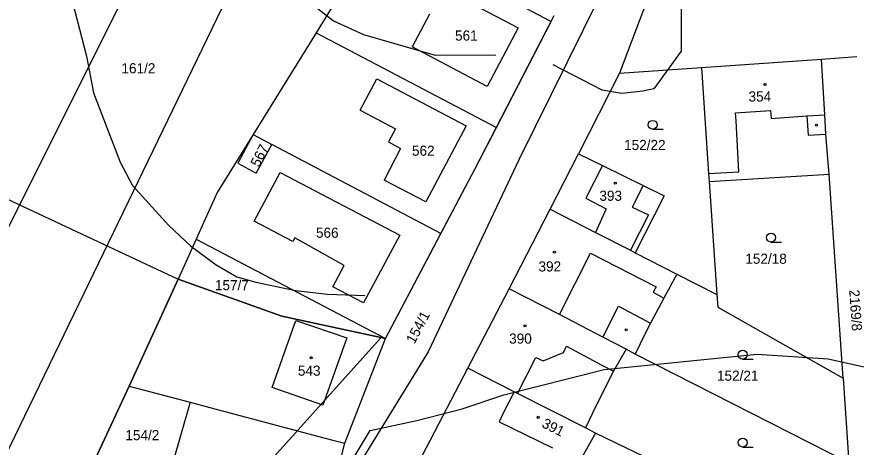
# Model space of a CAD drawing. Extents: x -555860 to -552701, y -1187050 to -1182291.
# Drawn here: x -554722 to -554581.3, y -1185302.4 to -1185230.2 of the extents above; entities that cross this region are included whole.
import ezdxf

# ---------------------------------------------------------------- set-up
doc = ezdxf.new("R2010")
doc.units = 0
for name, color, linetype in [('CYKLISTI_stav', 7, 'Continuous'), ('LEG_2b', 7, 'Continuous'), ('Level 25', 7, 'Continuous'), ('Level 32', 7, 'Continuous'), ('Level 40', 7, 'Continuous'), ('Level 41', 7, 'Continuous'), ('navrh_BV', 7, 'Continuous'), ('Poz předměty', 7, 'Continuous')]:
    doc.layers.add(name, color=color, linetype=linetype)

msp = doc.modelspace()

# ---------------------------------------------------------------- linework, layer by layer
at = {"layer": 'CYKLISTI_stav'}
for p, q in [((-554652.87, -1185229.81), (-554655.75, -1185235.27)), ((-554601.54, -1185246.33), (-554595.67, -1185245.93)), ((-554595.67, -1185245.93), (-554595.58, -1185247.27)), ((-554601.44, -1185247.68), (-554601.54, -1185246.33)), ((-554595.58, -1185247.27), (-554589.59, -1185246.86)), ((-554589.59, -1185246.86), (-554586.6, -1185246.65)), ((-554589.59, -1185246.86), (-554589.37, -1185250.05)), ((-554601.01, -1185256.23), (-554601.44, -1185247.68)), ((-554589.37, -1185250.05), (-554586.41, -1185249.88)), ((-554623.86, -1185255.18), (-554626.65, -1185260.66)), ((-554606.09, -1185256.51), (-554601.01, -1185256.23)), ((-554617.06, -1185258.49), (-554618.89, -1185262.12)), ((-554626.65, -1185260.66), (-554623.21, -1185262.45)), ((-554623.21, -1185262.45), (-554625, -1185266.39)), ((-554618.89, -1185262.12), (-554616.15, -1185263.46)), ((-554616.15, -1185263.46), (-554619.18, -1185269.37)), ((-554631.05, -1185280.15), (-554625.86, -1185269.85)), ((-554625.86, -1185269.85), (-554614.84, -1185275.52)), ((-554614.84, -1185275.52), (-554615.36, -1185276.41)), ((-554615.36, -1185276.41), (-554613.56, -1185277.39)), ((-554623.8, -1185283.93), (-554621.18, -1185278.72)), ((-554621.18, -1185278.72), (-554615.82, -1185281.59)), ((-554679.22, -1185292.41), (-554676.83, -1185285.56)), ((-554630.41, -1185286.52), (-554629.88, -1185285.43)), ((-554629.88, -1185285.43), (-554623.94, -1185288.63)), ((-554633.82, -1185287.93), (-554630.41, -1185286.52)), ((-554638.09, -1185293.4), (-554635.02, -1185287.37)), ((-554635.02, -1185287.37), (-554633.82, -1185287.93)), ((-554623.94, -1185288.63), (-554622.01, -1185289.67)), ((-554638.67, -1185293.1), (-554640.47, -1185296.55)), ((-554640.47, -1185296.55), (-554641.17, -1185298.14)), ((-554641.17, -1185298.14), (-554632.24, -1185302.52))]:
    msp.add_line(p, q, dxfattribs=at)
for points in [[(-554655.35, -1185228.5), (-554653.06, -1185224.13), (-554638, -1185232.07), (-554643.16, -1185241.89), (-554655.75, -1185235.27)], [(-554664.45, -1185245.89), (-554661.69, -1185240.61), (-554646.7, -1185248.53), (-554653.45, -1185261.25), (-554660.46, -1185257.6)], [(-554664.45, -1185245.89), (-554658.55, -1185249), (-554659.72, -1185251.2), (-554657.7, -1185252.3), (-554660.46, -1185257.6)], [(-554677.86, -1185256.31), (-554657.85, -1185266.84), (-554663.92, -1185278.2), (-554669.05, -1185275.52), (-554667.15, -1185271.91), (-554675.45, -1185267.31), (-554675.78, -1185267.92), (-554682.23, -1185264.5), (-554677.86, -1185256.31)], [(-554676.83, -1185285.56), (-554675.24, -1185281.13), (-554666.69, -1185284.05)], [(-554666.69, -1185284.05), (-554670.72, -1185295.35), (-554679.22, -1185292.41)]]:
    msp.add_lwpolyline(points, dxfattribs=at)
at = {"layer": 'Level 25'}
for p, q in [((-554615.43, -1185249.09), (-554613.68, -1185249.09)), ((-554595.61, -1185267.99), (-554593.86, -1185267.99)), ((-554600.36, -1185287.64), (-554598.61, -1185287.64)), ((-554600.35, -1185302.36), (-554598.6, -1185302.36))]:
    msp.add_line(p, q, dxfattribs=at)
for centre, radius in [((-554596.6, -1185241.59), 0.175), ((-554615.43, -1185248.34), 0.75), ((-554587.97, -1185248.41), 0.175), ((-554621.71, -1185258.11), 0.175), ((-554595.61, -1185267.24), 0.75), ((-554631.92, -1185269.69), 0.175), ((-554636.84, -1185282.05), 0.175), ((-554619.87, -1185282.72), 0.175), ((-554600.36, -1185286.89), 0.75), ((-554672.7, -1185287.39), 0.175), ((-554634.63, -1185297.38), 0.175), ((-554600.35, -1185301.61), 0.75)]:
    msp.add_circle(centre, radius, dxfattribs=at)
at = {"layer": 'Level 32'}
msp.add_lwpolyline([(-554790.07, -1185451.89), (-554786.97, -1185444.66), (-554772.69, -1185415.93), (-554768.14, -1185406.83), (-554760.45, -1185393.79), (-554752.81, -1185380.83), (-554747.05, -1185371.06), (-554744.55, -1185366.82), (-554742.18, -1185362.81), (-554734.88, -1185350.42), (-554731.79, -1185345.18), (-554728.42, -1185339.33), (-554721.98, -1185328.15), (-554715.19, -1185316.37), (-554711.08, -1185309.23), (-554708.82, -1185304.31), (-554703.22, -1185292.14), (-554694.99, -1185274.23), (-554677.59, -1185280.44), (-554660.25, -1185284.19), (-554645.24, -1185255.79), (-554631.94, -1185230)], dxfattribs=at)
at = {"layer": 'Level 40'}
msp.add_lwpolyline([(-554698.72, -1185194.06), (-554690.44, -1185208.16), (-554682.81, -1185217.44), (-554675.05, -1185225.21), (-554672.47, -1185228.16), (-554668.96, -1185230.89), (-554663.93, -1185233.19), (-554651.92, -1185236.65), (-554641.72, -1185236.6)], dxfattribs=at)
at = {"layer": 'Level 41'}
for points in [[(-554713.48, -1185224.71), (-554710.34, -1185236.84), (-554709.16, -1185242.96), (-554704.72, -1185254.6), (-554702.64, -1185258.49), (-554696.55, -1185265.22), (-554692.93, -1185268.61), (-554688.63, -1185271.8), (-554685.16, -1185273.8), (-554681.98, -1185274.71), (-554675.32, -1185276.1), (-554669.94, -1185276.74), (-554663.68, -1185276.98)], [(-554610.69, -1185228.58), (-554610.69, -1185235.99), (-554615.25, -1185242.28), (-554617.09, -1185242.72), (-554620.62, -1185243.08), (-554623.88, -1185242.54), (-554632.12, -1185238.29)], [(-554661.07, -1185284.09), (-554684.28, -1185309.94), (-554690.52, -1185315.19), (-554697.2, -1185318.72), (-554702.61, -1185320.72), (-554707.59, -1185321.19), (-554712.5, -1185320.94), (-554716.92, -1185319.77), (-554721.47, -1185317.69), (-554727.32, -1185313.67), (-554730.65, -1185310.48), (-554735.08, -1185304.94), (-554738.69, -1185298.97), (-554741.46, -1185292.87), (-554743.67, -1185284.74)], [(-554722.4, -1185366.31), (-554717.47, -1185364.7), (-554705.97, -1185359.71), (-554700.79, -1185356.74), (-554693.27, -1185349.06), (-554682.78, -1185332.7), (-554662.8, -1185299.59), (-554654.95, -1185297.94), (-554647.39, -1185295.96), (-554640.4, -1185293.59), (-554623.56, -1185289.36), (-554597.95, -1185286.77), (-554586.03, -1185287.6), (-554579.76, -1185288.98), (-554574.38, -1185290.52), (-554563.19, -1185295.17), (-554559.7, -1185298.39)]]:
    msp.add_lwpolyline(points, dxfattribs=at)
at = {"layer": 'navrh_BV'}
for p, q in [((-554690.88, -1185200.25), (-554756.64, -1185331.95)), ((-554741.42, -1185340.01), (-554676.85, -1185206.41)), ((-554616.52, -1185211.09), (-554637.82, -1185254.08)), ((-554661.31, -1185215.81), (-554671.87, -1185232.89)), ((-554614.52, -1185222.49), (-554621, -1185239.68)), ((-554645.44, -1185224.17), (-554632.46, -1185231)), ((-554632.46, -1185231), (-554631.94, -1185230)), ((-554641.64, -1185248.81), (-554632.46, -1185231)), ((-554671.87, -1185232.89), (-554682.43, -1185249.97)), ((-554671.87, -1185232.89), (-554641.64, -1185248.81)), ((-554607.25, -1185238.73), (-554587.16, -1185237.33)), ((-554587.16, -1185237.33), (-554581.21, -1185236.88)), ((-554586.6, -1185246.65), (-554587.16, -1185237.33)), ((-554621, -1185239.68), (-554607.25, -1185238.73)), ((-554607.25, -1185238.73), (-554606.64, -1185248.04)), ((-554621, -1185239.68), (-554627.88, -1185253.22)), ((-554586.41, -1185249.88), (-554586.6, -1185246.65)), ((-554645.24, -1185255.79), (-554641.64, -1185248.81)), ((-554606.64, -1185248.04), (-554606.09, -1185256.51)), ((-554682.43, -1185249.97), (-554688.42, -1185259.67)), ((-554682.43, -1185249.97), (-554684.99, -1185254.79)), ((-554682.43, -1185249.97), (-554679.28, -1185251.63)), ((-554585.95, -1185255.39), (-554586.41, -1185249.88)), ((-554681.88, -1185256.45), (-554679.28, -1185251.63)), ((-554650.93, -1185266.55), (-554679.28, -1185251.63)), ((-554632.63, -1185262.48), (-554627.88, -1185253.22)), ((-554627.88, -1185253.22), (-554623.86, -1185255.18)), ((-554637.82, -1185254.08), (-554653.1, -1185286.43)), ((-554684.99, -1185254.79), (-554681.88, -1185256.45)), ((-554650.93, -1185266.55), (-554645.24, -1185255.79)), ((-554623.86, -1185255.18), (-554617.06, -1185258.49)), ((-554585.87, -1185256.63), (-554585.95, -1185255.39)), ((-554606.09, -1185256.51), (-554605.99, -1185257.86)), ((-554605.99, -1185257.86), (-554585.87, -1185256.63)), ((-554583.52, -1185290.79), (-554585.87, -1185256.63)), ((-554617.06, -1185258.49), (-554613.52, -1185260.22)), ((-554605.99, -1185257.86), (-554604.66, -1185276.8)), ((-554688.42, -1185259.67), (-554691.95, -1185267.5)), ((-554613.52, -1185260.22), (-554618.37, -1185269.78)), ((-554639.48, -1185275.83), (-554632.63, -1185262.48)), ((-554632.63, -1185262.48), (-554625, -1185266.39)), ((-554660.25, -1185284.19), (-554650.93, -1185266.55)), ((-554625, -1185266.39), (-554619.18, -1185269.37)), ((-554691.95, -1185267.5), (-554694.99, -1185274.23)), ((-554691.95, -1185267.5), (-554660.25, -1185284.19)), ((-554619.18, -1185269.37), (-554618.37, -1185269.78)), ((-554618.37, -1185269.78), (-554611.38, -1185273.36)), ((-554694.99, -1185274.23), (-554703.22, -1185292.14)), ((-554677.59, -1185280.44), (-554694.99, -1185274.23)), ((-554611.38, -1185273.36), (-554613.56, -1185277.39)), ((-554611.38, -1185273.36), (-554604.66, -1185276.8)), ((-554646.4, -1185289.14), (-554639.48, -1185275.83)), ((-554631.05, -1185280.15), (-554639.48, -1185275.83)), ((-554604.66, -1185276.8), (-554604.51, -1185278.94)), ((-554613.56, -1185277.39), (-554615.82, -1185281.59)), ((-554604.51, -1185278.94), (-554583.52, -1185290.79)), ((-554660.25, -1185284.19), (-554677.59, -1185280.44)), ((-554623.8, -1185283.93), (-554631.05, -1185280.15)), ((-554615.82, -1185281.59), (-554616.68, -1185283.34)), ((-554667.06, -1185301.73), (-554660.25, -1185284.19)), ((-554619.9, -1185285.98), (-554623.8, -1185283.93)), ((-554616.68, -1185283.34), (-554618.36, -1185286.8)), ((-554653.1, -1185286.43), (-554664.77, -1185305.4)), ((-554619.9, -1185285.98), (-554622.01, -1185289.67)), ((-554618.36, -1185286.8), (-554619.9, -1185285.98)), ((-554582.54, -1185305.03), (-554618.36, -1185286.8)), ((-554654.76, -1185305.13), (-554646.4, -1185289.14)), ((-554638.67, -1185293.1), (-554646.4, -1185289.14)), ((-554622.01, -1185289.67), (-554624.89, -1185295.41)), ((-554583.52, -1185290.79), (-554582.54, -1185305.03)), ((-554703.22, -1185292.14), (-554708.82, -1185304.31)), ((-554703.22, -1185292.14), (-554692.98, -1185294.86)), ((-554638.09, -1185293.4), (-554638.67, -1185293.1)), ((-554626.72, -1185299.17), (-554638.09, -1185293.4)), ((-554692.98, -1185294.86), (-554695.89, -1185304.98)), ((-554692.98, -1185294.86), (-554689.7, -1185295.73)), ((-554624.89, -1185295.41), (-554626.72, -1185299.17)), ((-554689.7, -1185295.73), (-554670.57, -1185300.8)), ((-554625.03, -1185300.03), (-554626.72, -1185299.17)), ((-554670.57, -1185300.8), (-554669.29, -1185301.14)), ((-554625.03, -1185300.03), (-554627.79, -1185304.9)), ((-554581.44, -1185321.01), (-554625.03, -1185300.03)), ((-554670.31, -1185314.54), (-554667.06, -1185301.73)), ((-554669.29, -1185301.14), (-554667.06, -1185301.73))]:
    msp.add_line(p, q, dxfattribs=at)
at = {"layer": 'Poz předměty'}
msp.add_lwpolyline([(-554739.02, -1185253.58), (-554694.99, -1185274.23)], dxfattribs=at)

# ---------------------------------------------------------------- texts
at = {"layer": 'LEG_2b'}
for s, p in [('561', (-554648.57, -1185234.22)), ('161/2', (-554704.49, -1185239.71)), ('354', (-554599.37, -1185244.43)), ('562', (-554655.79, -1185253.53)), ('152/22', (-554620.23, -1185252.57)), ('393', (-554624.37, -1185261.08)), ('566', (-554671.88, -1185267.28)), ('152/18', (-554599.91, -1185271.64)), ('392', (-554634.58, -1185272.93)), ('157/7', (-554688.82, -1185276.07)), ('390', (-554639.5, -1185285.03)), ('543', (-554674.91, -1185290.41)), ('152/21', (-554604.66, -1185291.25)), ('154/2', (-554703.83, -1185301.22))]:
    msp.add_text(s, height=1.7, dxfattribs=at).set_placement(p)
for s, rotation, p in [('567', 63, (-554681.44, -1185255.55)), ('2169/8', 274, (-554582.5, -1185276.03)), ('154/1', 62, (-554655.38, -1185285.18)), ('391', 333, (-554634.17, -1185298.95))]:
    msp.add_text(s, height=1.7, rotation=rotation, dxfattribs=at).set_placement(p)

doc.saveas('drawing.dxf')
